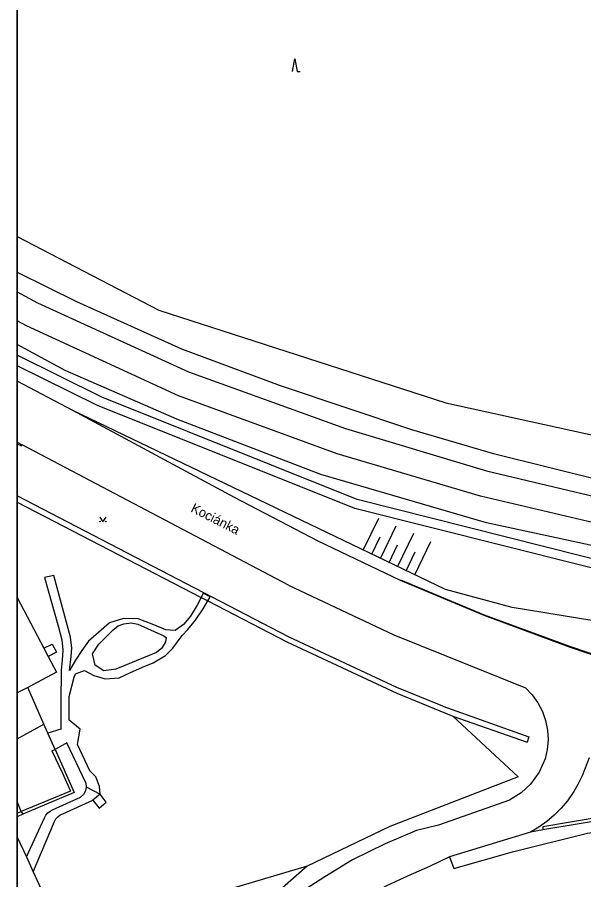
# Model space of a CAD drawing. Extents: x -598233 to -596890, y -1157848 to -1156431.
# Drawn here: x -598232.9 to -598143.6, y -1157273.5 to -1157137.4 of the extents above; entities that cross this region are included whole.
import ezdxf

# ---------------------------------------------------------------- set-up
doc = ezdxf.new("R2010")
doc.units = 0
for name, color, linetype in [('Level 10', 7, 'Continuous'), ('Level 11', 7, 'Continuous'), ('Level 13', 7, 'Continuous'), ('Level 14', 7, 'Continuous'), ('Level 15', 7, 'Continuous'), ('Level 36', 7, 'Continuous'), ('Level 5', 7, 'Continuous'), ('Level 50', 7, 'Continuous'), ('Level 7', 7, 'Continuous'), ('Level 9', 7, 'Continuous'), ('Vrstva 60', 7, 'Continuous'), ('zajmove_uzemi', 7, 'Continuous')]:
    doc.layers.add(name, color=color, linetype=linetype)

msp = doc.modelspace()

# ---------------------------------------------------------------- linework, layer by layer
at = {"layer": 'Level 10'}
for p, q in [((-598224.13, -1157199.44), (-598232.8901, -1157194.8063)), ((-598232.8901, -1157204.4603), (-598232.13, -1157204.86))]:
    msp.add_line(p, q, dxfattribs=at)
for points in [[(-598172.49, -1157226.27), (-598185.45, -1157220.04), (-598198.67, -1157213.17), (-598224.13, -1157199.44)], [(-598190.1599, -1157226.99), (-598232.13, -1157204.86)], [(-598190.1599, -1157226.99), (-598173.55, -1157234.85), (-598152.77, -1157243.19)], [(-598145.84, -1157236.77), (-598159.27, -1157231.8), (-598172.49, -1157226.27)], [(-598075.1599, -1157247.49), (-598084.15, -1157247.71), (-598093.14, -1157247.48), (-598102.11, -1157246.8), (-598111.04, -1157245.67), (-598119.89, -1157244.1), (-598128.6599, -1157242.09), (-598137.32, -1157239.65), (-598145.84, -1157236.77)], [(-598152.77, -1157243.19), (-598151.7199, -1157244.29), (-598150.82, -1157245.54), (-598150.12, -1157246.9), (-598149.61, -1157248.34), (-598149.31, -1157249.84), (-598149.2199, -1157251.37), (-598149.35, -1157252.9), (-598149.69, -1157254.39), (-598150.61, -1157256.5), (-598151.9699, -1157258.37)], [(-598142.73, -1157254.2199), (-598143.85, -1157257.04)], [(-598143.85, -1157257.04), (-598144.51, -1157258.43), (-598145.14, -1157259.53), (-598146.17, -1157261.01), (-598147.1599, -1157262.19), (-598148.25, -1157263.28), (-598149.42, -1157264.27), (-598150.68, -1157265.1599), (-598152.01, -1157265.94)], [(-598151.9699, -1157258.37), (-598153.44, -1157259.73)], [(-598153.44, -1157259.73), (-598155.3, -1157260.88), (-598166.5, -1157264.86)], [(-598166.5, -1157264.86), (-598169.94, -1157265.67), (-598174.9, -1157267.8), (-598180.05, -1157270.32), (-598184.4, -1157272.98), (-598188.1, -1157275.38), (-598191.83, -1157278.19), (-598195.58, -1157281.49), (-598198.9099, -1157284.86), (-598201.2199, -1157287.92), (-598203.6599, -1157292.32), (-598205.11, -1157296.36), (-598206.19, -1157300.79), (-598209.14, -1157321.63), (-598209.42, -1157323.57), (-598211.71, -1157328.93), (-598214.02, -1157332.37), (-598218.17, -1157336.4099)], [(-598152.01, -1157265.94), (-598164.78, -1157269.84)], [(-598164.78, -1157269.84), (-598167.92, -1157271.38), (-598171.27, -1157272.82), (-598174.77, -1157274.46), (-598178.31, -1157276.45), (-598181.7199, -1157278.53), (-598185.36, -1157280.98), (-598188.78, -1157283.56), (-598191.9, -1157286.34), (-598194.3, -1157288.93), (-598197.19, -1157293.15), (-598199.36, -1157298.01), (-598200.56, -1157302.25), (-598202.71, -1157321.99), (-598203.43, -1157325.24), (-598203.75, -1157326.35)]]:
    msp.add_lwpolyline(points, dxfattribs=at)
at = {"layer": 'Level 11'}
for p, q in [((-598232.8901, -1157213.9051), (-598203.9099, -1157228.93)), ((-598232.26, -1157262.67), (-598232.8901, -1157261.0949)), ((-598232.8901, -1157262.9572), (-598232.26, -1157262.67)), ((-598232, -1157263.13), (-598232.8901, -1157263.5414))]:
    msp.add_line(p, q, dxfattribs=at)
for points in [[(-598232.8901, -1157171.9848), (-598210.59, -1157183.62), (-598165.35, -1157198.24), (-598123.48, -1157207.46)], [(-598232.8901, -1157177.6233), (-598223.53, -1157182.26), (-598207.02, -1157189.72), (-598191.46, -1157195.51), (-598170.75, -1157202.42), (-598158.05, -1157206.15), (-598139.63, -1157210.75), (-598120.82, -1157214.64), (-598113.2, -1157216.15), (-598111.7, -1157215.33)], [(-598076.69, -1157233.76), (-598132.33, -1157222.9), (-598158.92, -1157217.18), (-598185.03, -1157209.56), (-598207.73, -1157200.83), (-598225.36, -1157193.13), (-598232.8901, -1157189.015)], [(-598076.69, -1157233.76), (-598132.24, -1157225.39), (-598179.31, -1157213.48), (-598219.56, -1157197.32), (-598232.8901, -1157190.7005)], [(-598076.82, -1157234.35), (-598132.4099, -1157226.78), (-598179.67, -1157214.9099), (-598220.23, -1157198.6599), (-598232.8901, -1157192.3808)], [(-598165.83, -1157246.1), (-598173.05, -1157243.11), (-598190.1599, -1157235.15), (-598232.8901, -1157212.93)], [(-598224.38, -1157238.24), (-598224.27, -1157236.95), (-598224.52, -1157235.2199), (-598227.12, -1157225.48), (-598228.6, -1157225.76), (-598226.39, -1157233.64), (-598225.84, -1157235.61), (-598225.7, -1157237.25), (-598225.81, -1157238.8), (-598225.98, -1157240.4099), (-598226.01, -1157245.4), (-598226.02, -1157249.7199), (-598228.07, -1157250.35), (-598228.69, -1157248.92)], [(-598202.87, -1157229.4699), (-598202.5, -1157228.83), (-598203.56, -1157228.26), (-598203.9099, -1157228.93)], [(-598219.82, -1157259.9699), (-598219.93, -1157258.77), (-598220.51, -1157257.24), (-598221.44, -1157256.28), (-598223.39, -1157252.12), (-598223, -1157249.73), (-598224.69, -1157248.29), (-598224.69, -1157244.57), (-598223.93, -1157241.53), (-598223.7199, -1157241), (-598222.29, -1157240.43), (-598220.81, -1157241.25), (-598219.05, -1157241.78), (-598216.85, -1157241.6), (-598215.15, -1157240.84), (-598213.14, -1157239.94), (-598211.45, -1157239.23), (-598209.5, -1157238.1), (-598208.39, -1157236.9099), (-598206.9099, -1157234.9099), (-598205.98, -1157234.01), (-598204.78, -1157232.52), (-598203.59, -1157230.7199), (-598202.87, -1157229.4699)], [(-598203.9099, -1157228.93), (-598204.55, -1157230.1599), (-598205.6, -1157231.89), (-598206.69, -1157233.18), (-598207.98, -1157234.14), (-598209.45, -1157234.04), (-598211.63, -1157233.15), (-598213.81, -1157232.29), (-598216.14, -1157232.26), (-598218.33, -1157232.95), (-598220.1, -1157234.48), (-598221.67, -1157235.85), (-598222.7199, -1157237.28), (-598223.7, -1157238.8), (-598224.65, -1157240.4699)], [(-598203.9099, -1157228.93), (-598202.87, -1157229.4699)], [(-598202.87, -1157229.4699), (-598190.4, -1157235.94), (-598173.05, -1157244.01), (-598164.2199, -1157247.64)], [(-598217.81, -1157234.1), (-598216.98, -1157233.43), (-598216.11, -1157233.07), (-598214.93, -1157232.94), (-598213.89, -1157233.1599)], [(-598220.03, -1157236.31), (-598217.81, -1157234.1)], [(-598213.89, -1157233.1599), (-598209.76, -1157234.99), (-598209.4, -1157235.25), (-598209.51, -1157235.92), (-598210.12, -1157236.94), (-598210.96, -1157237.62), (-598217.33, -1157240.23)], [(-598228.69, -1157236.9099), (-598227.38, -1157236.28), (-598226.7199, -1157237.55), (-598228.02, -1157238.26)], [(-598221.04, -1157237.83), (-598220.03, -1157236.31)], [(-598224.65, -1157240.4699), (-598224.38, -1157238.24)], [(-598220.59, -1157239.6), (-598221.04, -1157237.83)], [(-598219.26, -1157240.51), (-598220.59, -1157239.6)], [(-598217.33, -1157240.23), (-598219.26, -1157240.51)], [(-598165.83, -1157246.1), (-598152.23, -1157250.92), (-598152.51, -1157251.75)], [(-598164.2199, -1157247.64), (-598152.51, -1157251.75)], [(-598226.93, -1157252.92), (-598228.07, -1157250.35)], [(-598222.1, -1157258.18), (-598225.05, -1157251.87), (-598226.93, -1157252.92)], [(-598226.93, -1157252.92), (-598223.9099, -1157259.67), (-598232, -1157263.13)], [(-598227.42, -1157253.13), (-598226.93, -1157252.92)], [(-598227.42, -1157253.13), (-598225.75, -1157256.63)], [(-598225.75, -1157256.63), (-598224.52, -1157259.46)], [(-598222.1, -1157258.18), (-598222.01, -1157258.81), (-598222.13, -1157259.44), (-598222.45, -1157259.99), (-598222.93, -1157260.4099)], [(-598222.01, -1157258.81), (-598219.82, -1157259.97)], [(-598224.52, -1157259.46), (-598232.26, -1157262.67)], [(-598220.98, -1157260.9), (-598219.99, -1157262.14), (-598218.86, -1157261.23), (-598219.82, -1157259.9699)], [(-598219.82, -1157259.9699), (-598220.98, -1157260.9)], [(-598106.11, -1157258.95), (-598129.1599, -1157261.61), (-598150.06, -1157265.09), (-598150.03, -1157265.6)], [(-598106.09, -1157259.44), (-598129.12, -1157262.05), (-598131.17, -1157262.4), (-598136.52, -1157263.3), (-598144.32, -1157264.62), (-598150.03, -1157265.6)], [(-598227.31, -1157262.4099), (-598222.93, -1157260.4099)], [(-598225.71, -1157263.05), (-598220.98, -1157260.9)], [(-598164.78, -1157269.84), (-598164.08, -1157271.7), (-598154.82, -1157269.06), (-598143, -1157266.11), (-598124.53, -1157263.42), (-598105.61, -1157261.14)], [(-598232.26, -1157262.67), (-598232, -1157263.13)], [(-598228.59, -1157263.67), (-598228.37, -1157263.26), (-598228.08, -1157262.9099), (-598227.7199, -1157262.62), (-598227.31, -1157262.4099)], [(-598231.44, -1157269.83), (-598228.59, -1157263.67)], [(-598227.03, -1157264.28), (-598226.81, -1157263.87), (-598226.51, -1157263.52), (-598226.13, -1157263.24), (-598225.71, -1157263.05)], [(-598230.37, -1157272.19), (-598227.03, -1157264.28)], [(-598150.03, -1157265.6), (-598152.01, -1157265.94)]]:
    msp.add_lwpolyline(points, dxfattribs=at)
at = {"layer": 'Level 13'}
for points in [[(-598232.8901, -1157180.7063), (-598229.68, -1157182.48), (-598205.89, -1157193.37), (-598181.17, -1157202.29), (-598158.92, -1157208.94), (-598130.17, -1157215.8), (-598110.28, -1157219.65)], [(-598111.25, -1157223.51), (-598131.28, -1157219.6599), (-598159.89, -1157212.94), (-598182.4699, -1157206.28), (-598207.49, -1157197.14), (-598231.42, -1157186.11), (-598232.8901, -1157185.2981)]]:
    msp.add_lwpolyline(points, dxfattribs=at)
at = {"layer": 'Level 14'}
for points in [[(-598154.86, -1157230.51), (-598165.4099, -1157227.7), (-598224.13, -1157199.44)], [(-598118.18, -1157235.69), (-598134.61, -1157233.83), (-598154.86, -1157230.51)], [(-598187.2, -1157271.32), (-598198.85, -1157281.57), (-598207.2199, -1157294.64), (-598209.61, -1157309.08), (-598212.32, -1157325.38), (-598215.73, -1157332.34), (-598218.33, -1157335.31)]]:
    msp.add_lwpolyline(points, dxfattribs=at)
at = {"layer": 'Level 15'}
for points in [[(-598178.35, -1157221.4699), (-598175.9099, -1157216.4099)], [(-598175.64, -1157222.78), (-598173.1599, -1157217.61)], [(-598172.94, -1157224.08), (-598170.4, -1157218.81)], [(-598176.99, -1157222.13), (-598175.68, -1157219.39)], [(-598174.29, -1157223.43), (-598172.95, -1157220.64)], [(-598170.24, -1157225.38), (-598167.7, -1157220.12)], [(-598171.59, -1157224.73), (-598170.1599, -1157221.76)]]:
    msp.add_lwpolyline(points, dxfattribs=at)
at = {"layer": 'Level 36'}
for points in [[(-598189.519, -1157145.9979), (-598189.144, -1157143.9979), (-598188.769, -1157145.9979), (-598188.269, -1157145.9979)], [(-598219.9, -1157216.27), (-598219.4, -1157217.02), (-598218.9, -1157216.27)]]:
    msp.add_lwpolyline(points, dxfattribs=at)
for centre in [(-598219.8502, -1157216.9698), (-598218.9508, -1157216.9698)]:
    msp.add_circle(centre, 0.05, dxfattribs=at)
at = {"layer": 'Level 5'}
for p, q in [((-598232.8901, -1157228.916), (-598228.69, -1157236.9099)), ((-598231.2199, -1157243.11), (-598232.8901, -1157243.9866)), ((-598232.8901, -1157251.2245), (-598228.69, -1157248.92)), ((-598232.8901, -1157266.7351), (-598231.44, -1157269.83))]:
    msp.add_line(p, q, dxfattribs=at)
for points in [[(-598228.69, -1157236.9099), (-598228.02, -1157238.26)], [(-598228.02, -1157238.26), (-598226.71, -1157240.7)], [(-598226.71, -1157240.7), (-598231.2199, -1157243.11)], [(-598228.69, -1157248.92), (-598231.2199, -1157243.11)], [(-598231.44, -1157269.83), (-598230.37, -1157272.19)], [(-598230.37, -1157272.19), (-598225.06, -1157283.77)]]:
    msp.add_lwpolyline(points, dxfattribs=at)
at = {"layer": 'Level 7'}
for points in [[(-598164.2199, -1157247.64), (-598153.95, -1157257.2199), (-598174.15, -1157265.06), (-598187.2, -1157271.32)], [(-598187.2, -1157271.32), (-598199.23, -1157274.88)]]:
    msp.add_lwpolyline(points, dxfattribs=at)
at = {"layer": 'Level 9'}
msp.add_line((-598232.8901, -1157204.6776), (-598232.2199, -1157205.03), dxfattribs=at)
for points in [[(-598145.81, -1157236.68), (-598159.23, -1157231.71), (-598172.45, -1157226.18)], [(-598075.17, -1157247.39), (-598084.15, -1157247.61), (-598093.14, -1157247.38), (-598102.1, -1157246.7), (-598111.03, -1157245.57), (-598119.87, -1157244), (-598128.64, -1157241.99), (-598137.29, -1157239.55), (-598145.81, -1157236.68)]]:
    msp.add_lwpolyline(points, dxfattribs=at)
at = {"layer": 'Vrstva 60'}
msp.add_lwpolyline([(-598232.8901, -1156430.8558), (-598232.8901, -1157835.5817), (-598232.81, -1157835.6), (-598231.24, -1157835.95), (-598223.73, -1157837.73), (-598218.75, -1157838.85), (-598190.54, -1157845.18), (-598175.89, -1157848.4611), (-598170.5079, -1157848.4611), (-598170.38, -1157848.22), (-598166.89, -1157841.65), (-598165.3, -1157838.66), (-598164.37, -1157836.9), (-598161.86, -1157832.18), (-598161.19, -1157830.95), (-598160.05, -1157828.86), (-598157.63, -1157824.55), (-598144.71, -1157839.14), (-598136.4065, -1157848.4611), (-597003.6644, -1157848.4611)], dxfattribs=at)
at = {"layer": 'zajmove_uzemi'}
msp.add_lwpolyline([(-598232.8901, -1156430.8558), (-596890.4624, -1156430.8558), (-596890.4624, -1157848.4611), (-598232.8901, -1157848.4611)], close=True, dxfattribs=at)

# ---------------------------------------------------------------- texts
at = {"layer": 'Level 50'}
msp.add_text('Kociánka', height=1.5, rotation=333.082307, dxfattribs=at).set_placement((-598205.6608, -1157215.3411))
msp.add_text('Kociánka', height=1.5, rotation=333.082307, dxfattribs=at).set_placement((-598205.6608, -1157215.3411))

doc.saveas('drawing.dxf')
